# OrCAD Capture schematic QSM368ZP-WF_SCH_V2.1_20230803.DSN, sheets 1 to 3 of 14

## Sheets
1 PAGE01-POWER: size A2; rev: V2.1
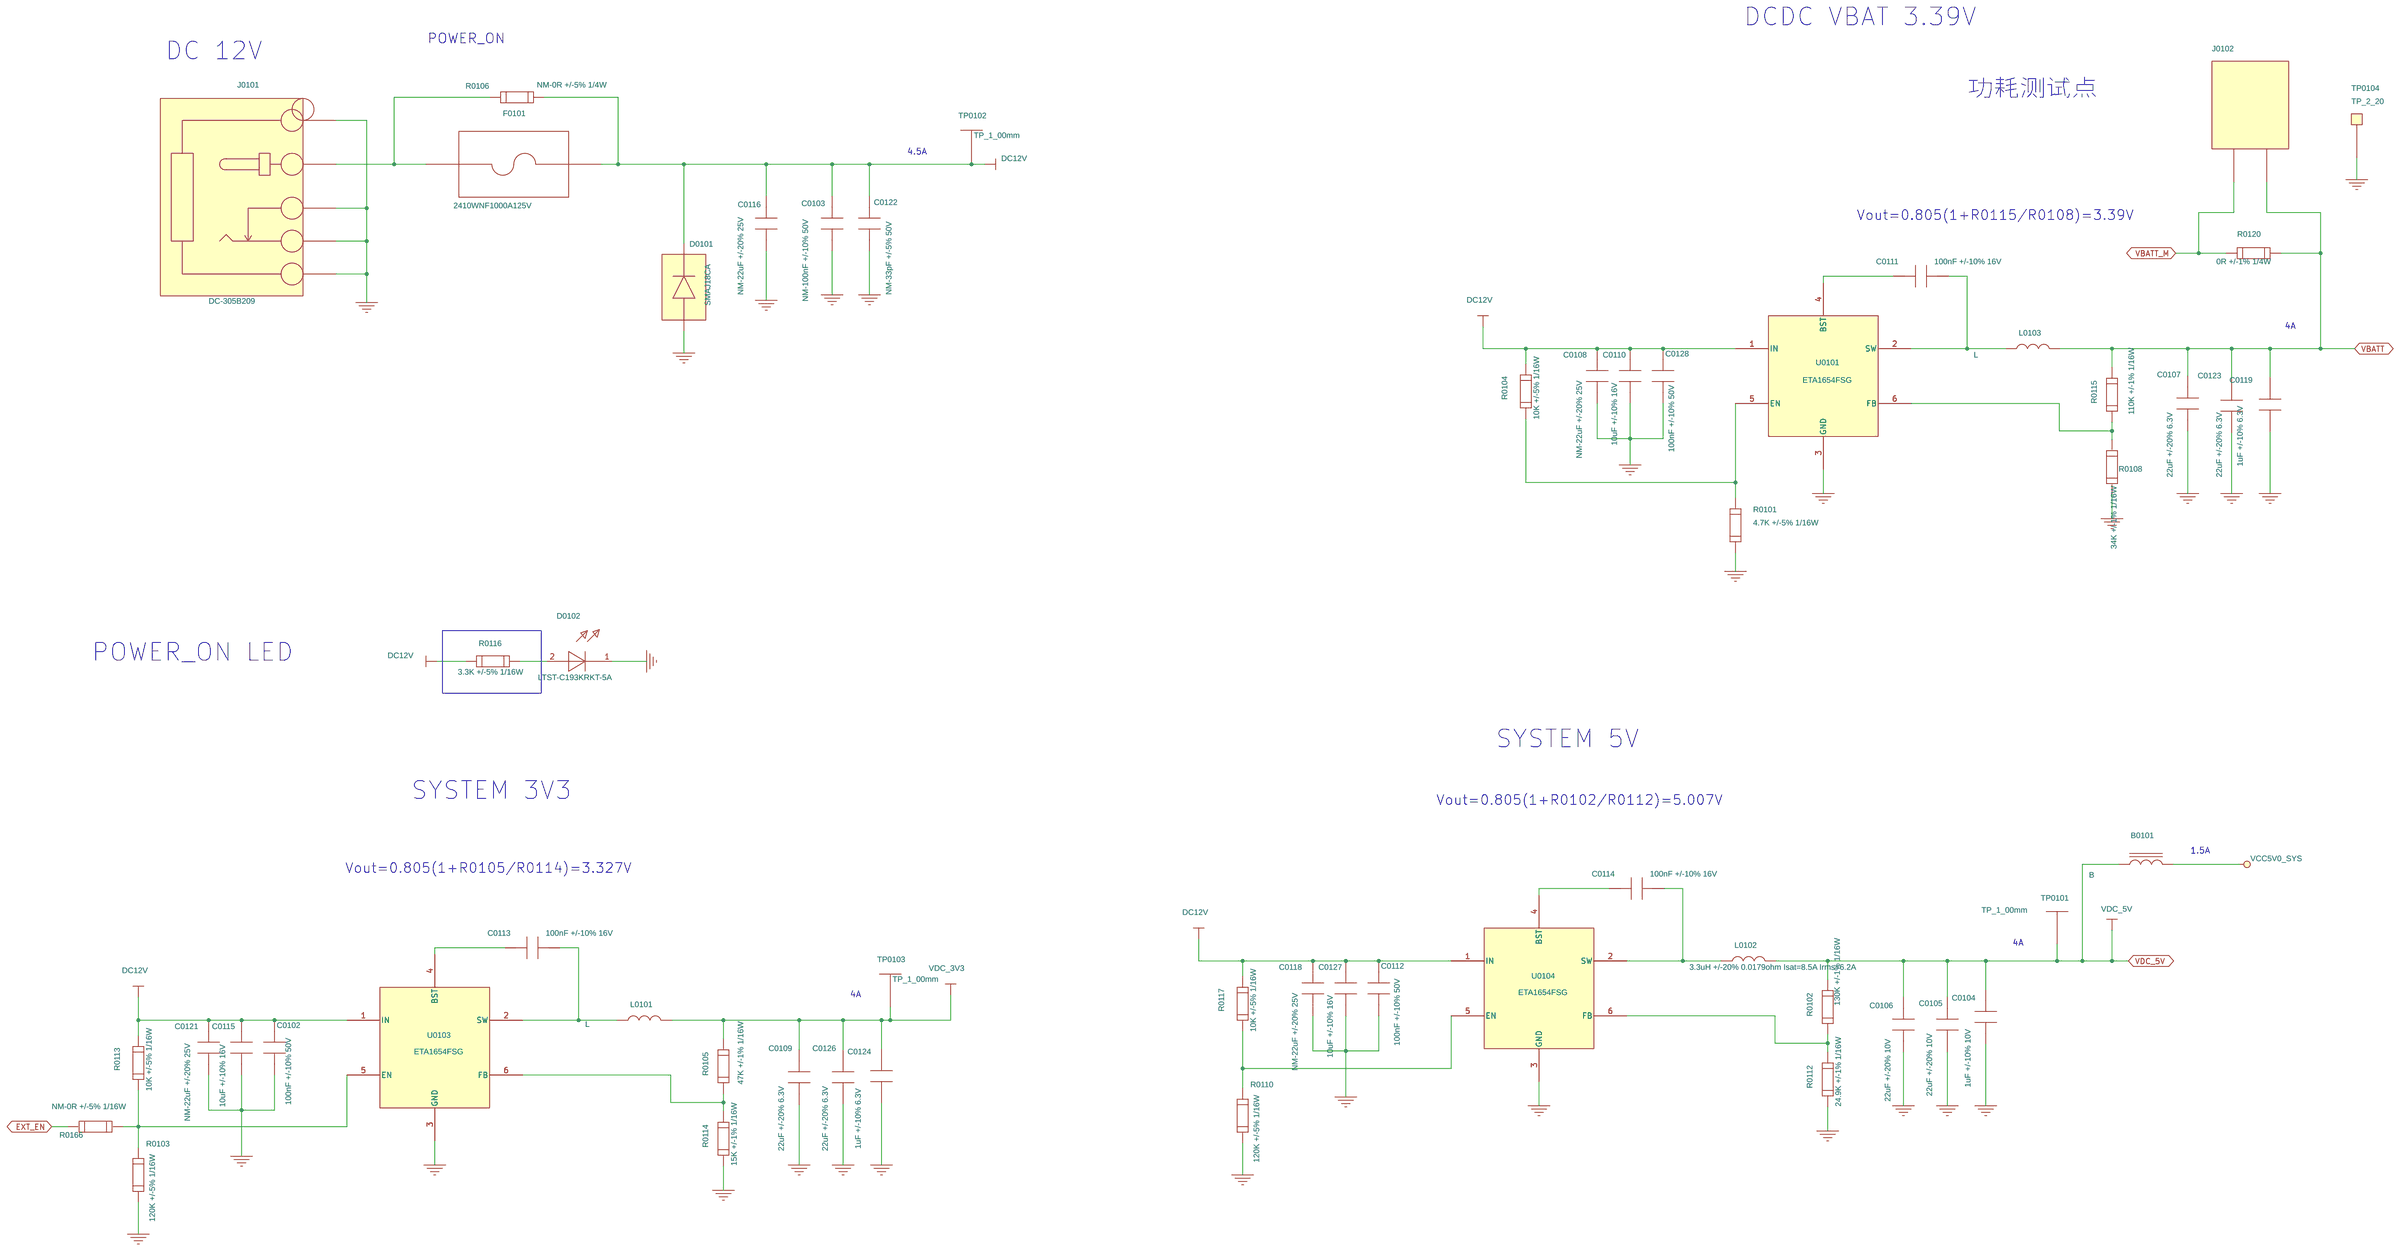
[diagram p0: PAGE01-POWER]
2 PAGE02-CAMERA: size A2
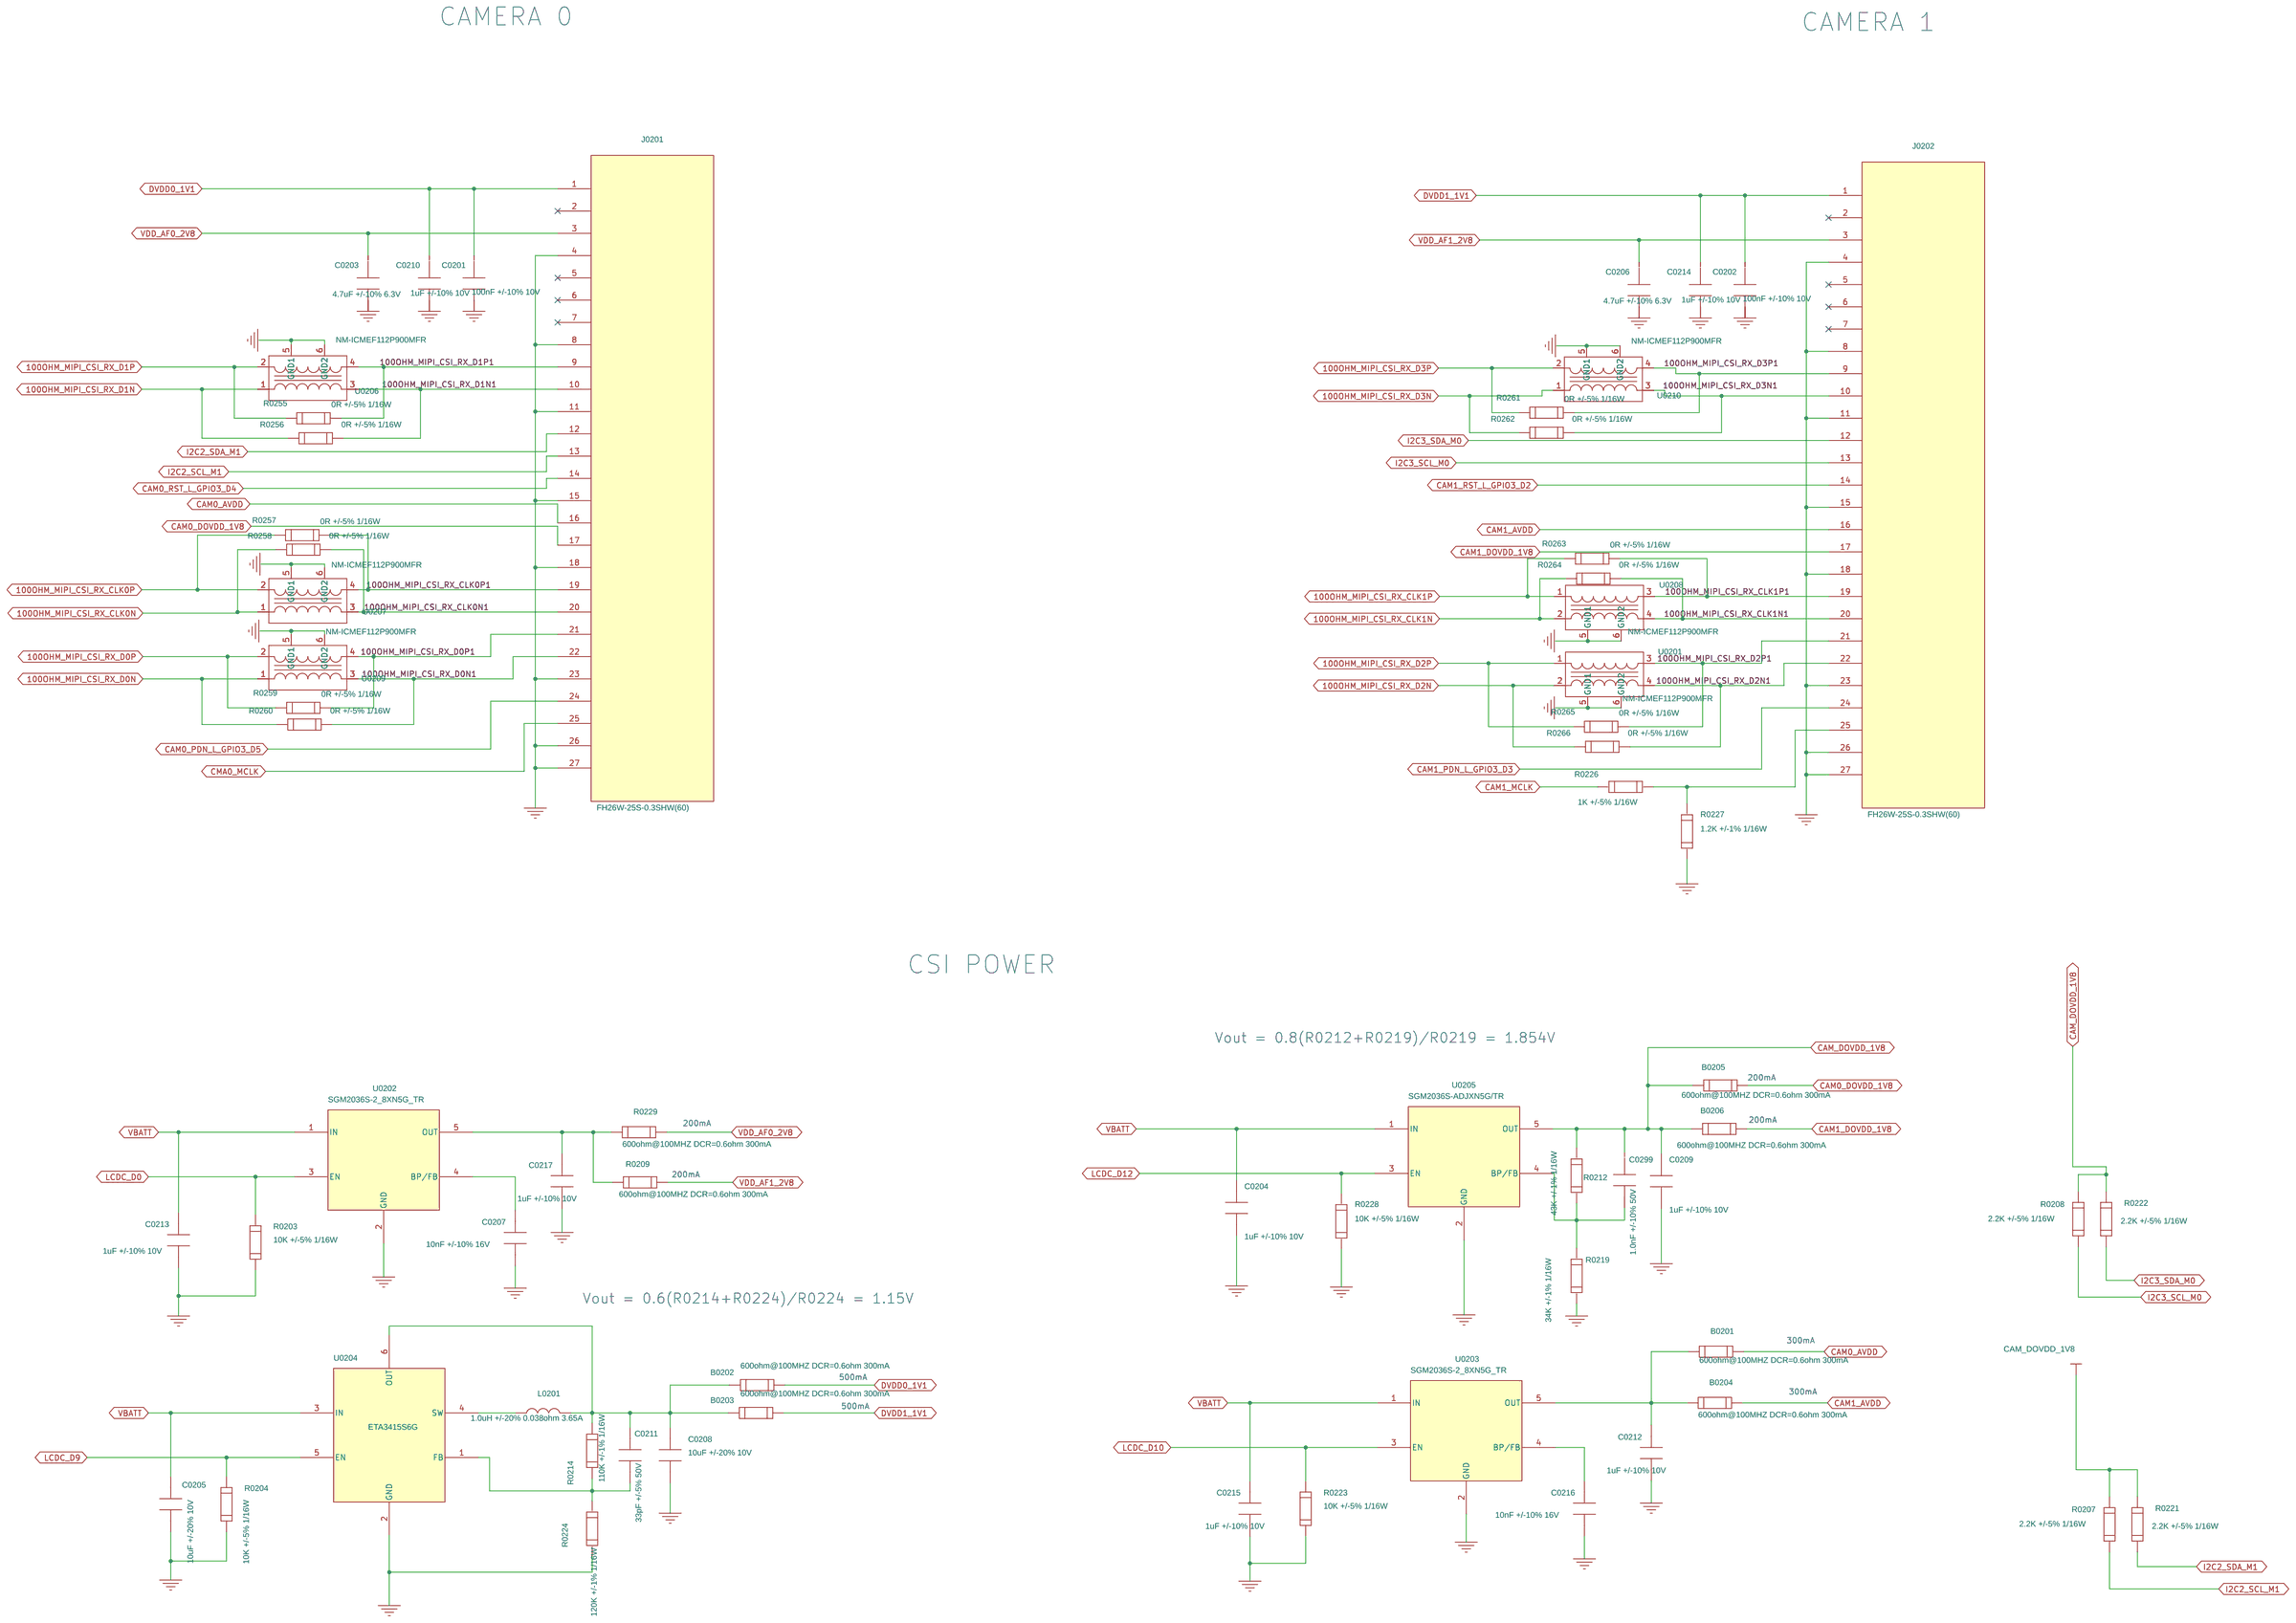
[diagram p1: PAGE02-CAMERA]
3 PAGE03-USB-OTG: size A2
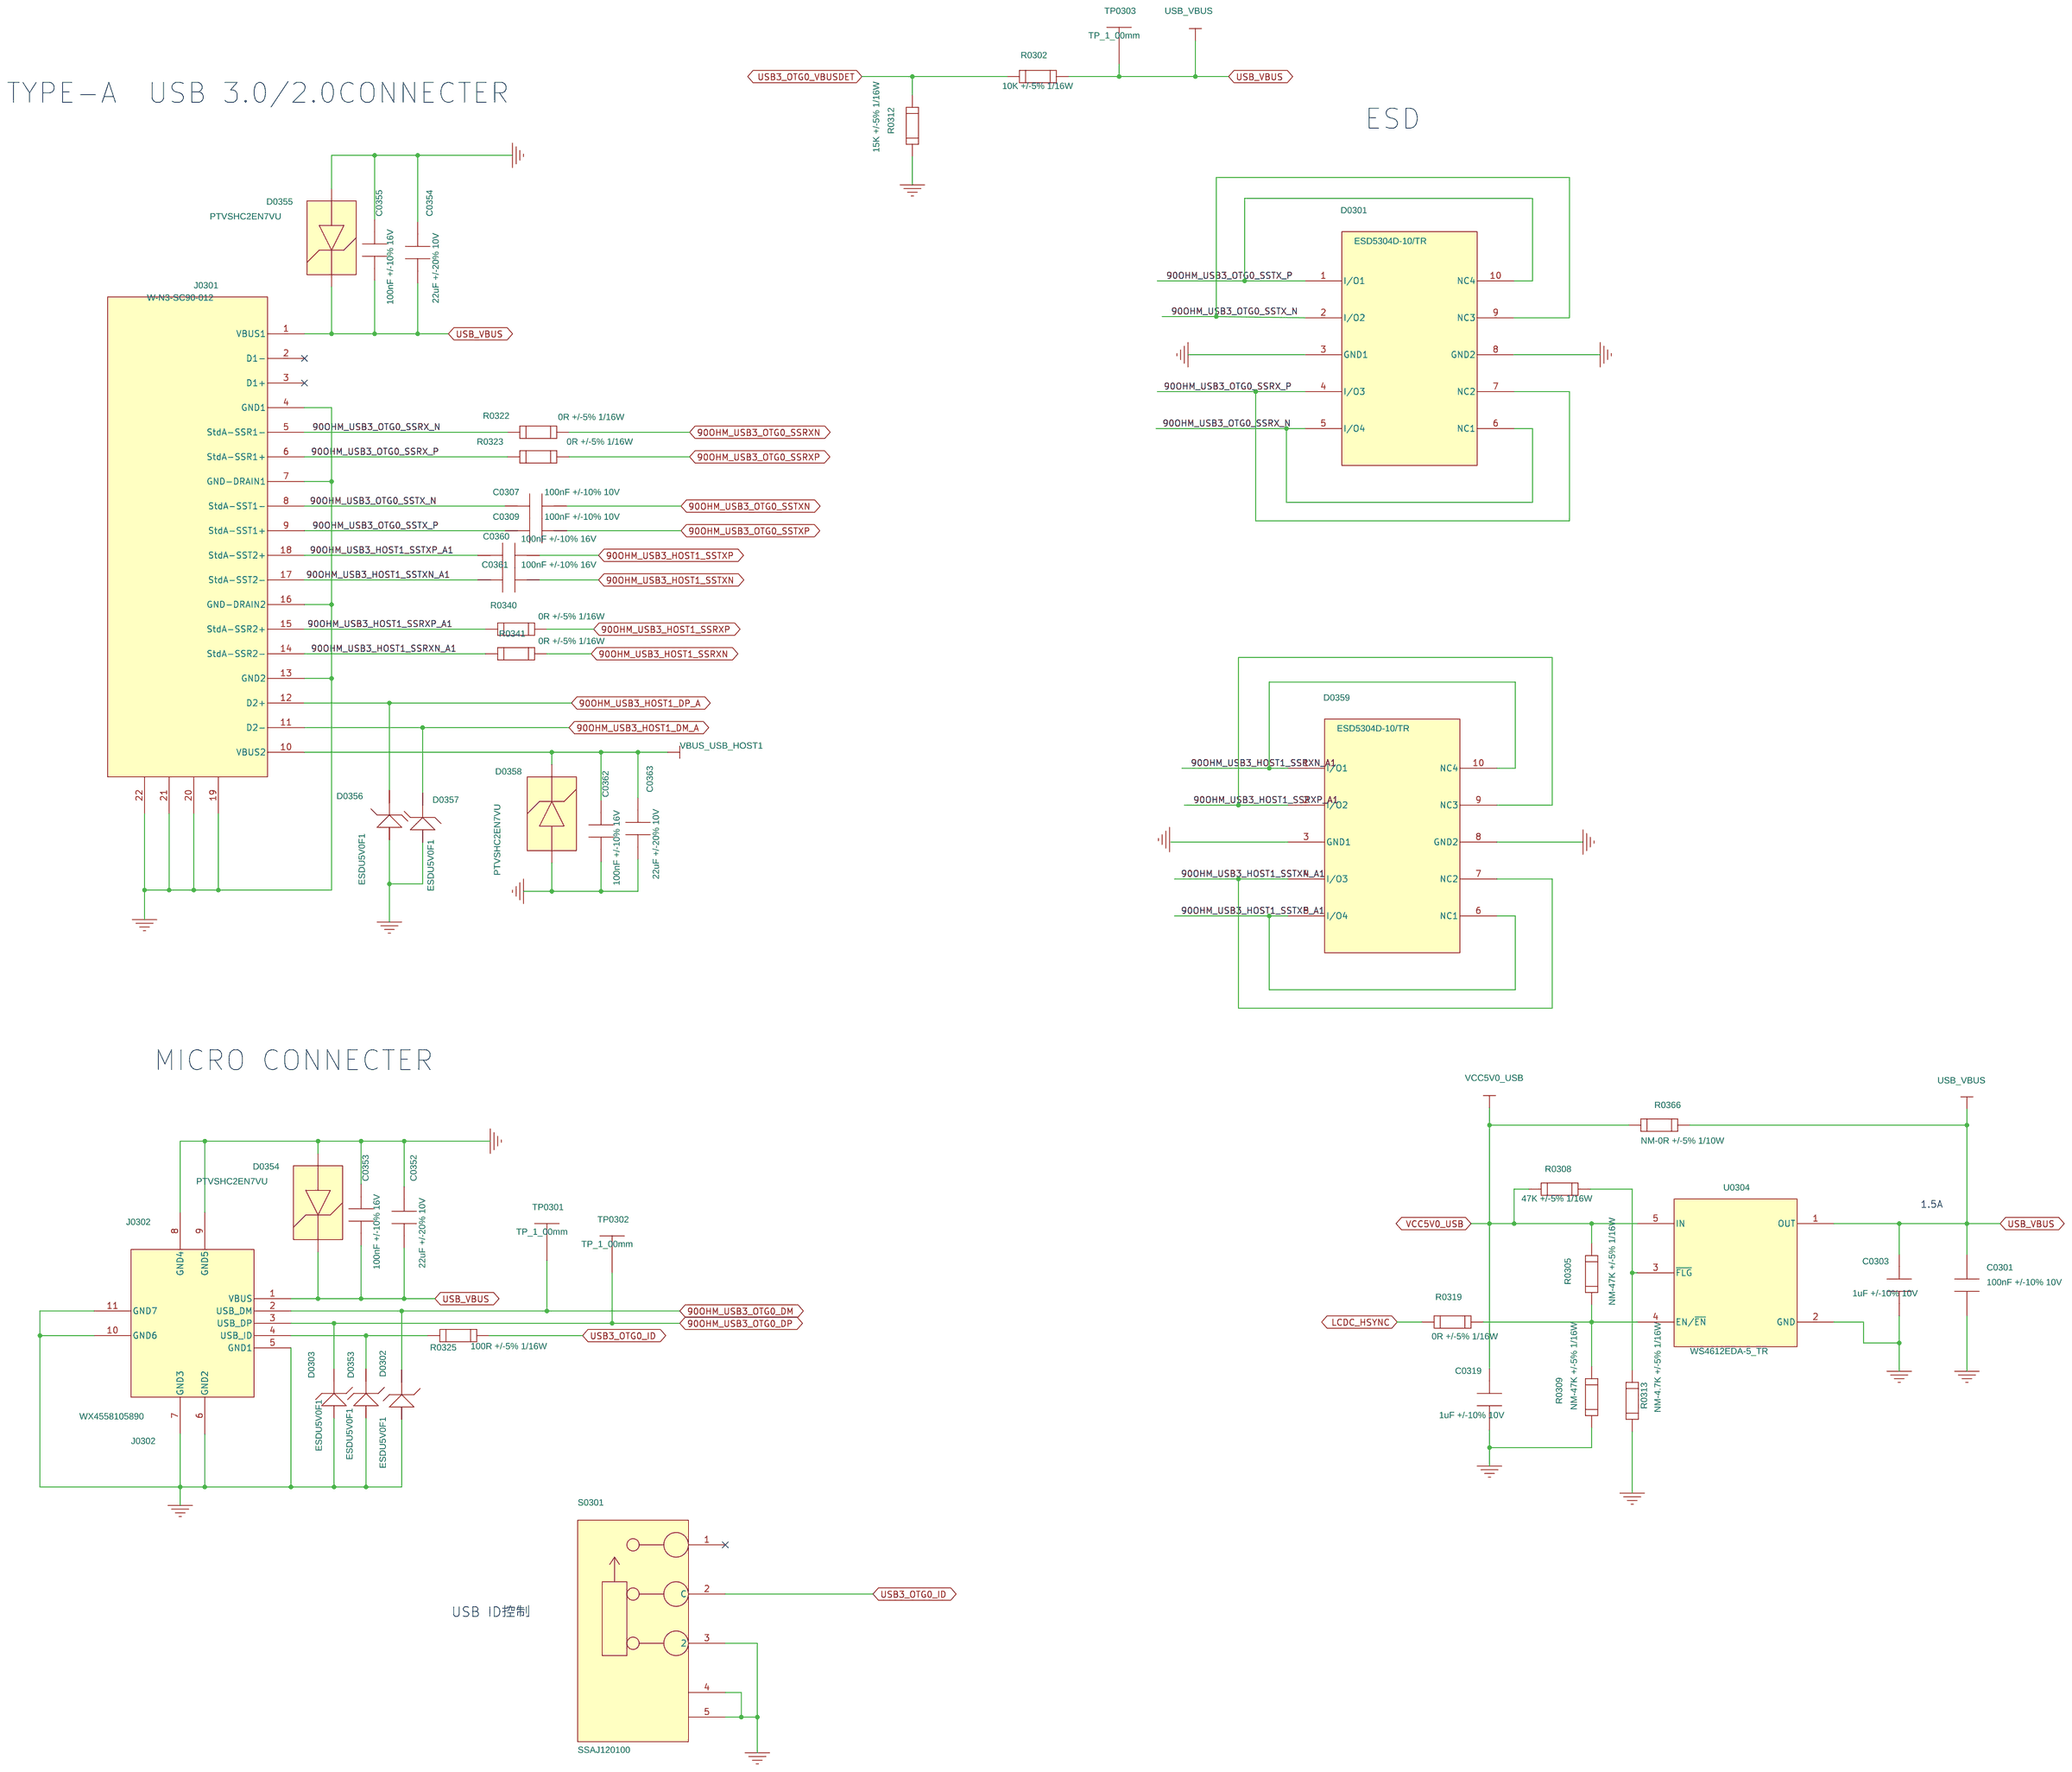
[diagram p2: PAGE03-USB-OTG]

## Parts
sheet PAGE01-POWER
B0101  B  [B-0402]
C0102  100nF +/-10% 50V  [C-0603]
C0103  NM-100nF +/-10% 50V  [C-0603]
C0104  1uF +/-10% 10V  [C-0402]
C0105  22uF +/-20% 10V  [c-0603_22_47uf_h1_00]
C0106  22uF +/-20% 10V  [c-0603_22_47uf_h1_00]
C0107  22uF +/-20% 6.3V  [c-0603_22_47uf_h1_00]
C0108  NM-22uF +/-20% 25V  [C-0805_H1_45]
C0109  22uF +/-20% 6.3V  [c-0603_22_47uf_h1_00]
C0110  10uF +/-10% 16V  [C-0805_H1_45]
C0111  100nF +/-10% 16V  [C-0402]
C0112  100nF +/-10% 50V  [C-0603]
C0113  100nF +/-10% 16V  [C-0402]
C0114  100nF +/-10% 16V  [C-0402]
C0115  10uF +/-10% 16V  [C-0805_H1_45]
C0116  NM-22uF +/-20% 25V  [C-0805_H1_45]
C0118  NM-22uF +/-20% 25V  [C-0805_H1_45]
C0119  1uF +/-10% 6.3V  [C-0402]
C0121  NM-22uF +/-20% 25V  [C-0805_H1_45]
C0122  NM-33pF +/-5% 50V  [C-0402]
C0123  22uF +/-20% 6.3V  [c-0603_22_47uf_h1_00]
C0124  1uF +/-10% 6.3V  [C-0402]
C0126  22uF +/-20% 6.3V  [c-0603_22_47uf_h1_00]
C0127  10uF +/-10% 16V  [C-0805_H1_45]
C0128  100nF +/-10% 50V  [C-0603]
D0101  SMAJ18CA  [SMAJ18CA]
D0102  LTST-C193KRKT-5A  [LTST-C193KRKT-5A]
F0101  2410WNF1000A125V  [2410WNF1000A125V]
J0101  DC-305B209  [DC-305B209]
J0102  NM-C2542VD10210G0101PK  [C2542VD10210G0101PK]
L0101  L  [L-SPM6530T-3R3M]
L0102  3.3uH +/-20% 0.0179ohm Isat=8.5A Irms=6.2A  [L-SPM6530T-3R3M]
L0103  L  [L-SPM6530T-3R3M]
R0101  4.7K +/-5% 1/16W  [R-0402]
R0102  130K +/-1% 1/16W  [R-0402]
R0103  120K +/-5% 1/16W  [R-0402]
R0104  10K +/-5% 1/16W  [R-0402]
R0105  47K +/-1% 1/16W  [R-0402]
R0106  NM-0R +/-5% 1/4W  [R-1206]
R0108  34K +/-1% 1/16W  [R-0402]
R0110  120K +/-5% 1/16W  [R-0402]
R0112  24.9K +/-1% 1/16W  [R-0402]
R0113  10K +/-5% 1/16W  [R-0402]
R0114  15K +/-1% 1/16W  [R-0402]
R0115  110K +/-1% 1/16W  [R-0402]
R0116  3.3K +/-5% 1/16W  [R-0402]
R0117  10K +/-5% 1/16W  [R-0402]
R0120  0R +/-1% 1/4W  [R-1206]
R0166  NM-0R +/-5% 1/16W  [R-0402]
TP0101  TP_1_00mm  [TP_1_00]
TP0102  TP_1_00mm  [TP_1_00]
TP0103  TP_1_00mm  [TP_1_00]
TP0104  TP_2_20  [TP_2_20]
U0101  ETA1654FSG  [ETA1654FSG]
U0103  ETA1654FSG  [ETA1654FSG]
U0104  ETA1654FSG  [ETA1654FSG]
sheet PAGE02-CAMERA
B0201  600ohm@100MHZ DCR=0.6ohm 300mA  [R-0402]
B0202  600ohm@100MHZ DCR=0.6ohm 300mA  [R-0402]
B0203  600ohm@100MHZ DCR=0.6ohm 300mA  [R-0402]
B0204  600ohm@100MHZ DCR=0.6ohm 300mA  [R-0402]
B0205  600ohm@100MHZ DCR=0.6ohm 300mA  [R-0402]
B0206  600ohm@100MHZ DCR=0.6ohm 300mA  [R-0402]
C0201  100nF +/-10% 10V  [C-0402]
C0202  100nF +/-10% 10V  [C-0402]
C0203  4.7uF +/-10% 6.3V  [C-0603]
C0204  1uF +/-10% 10V  [C-0402]
C0205  10uF +/-20% 10V  [c-0402_4_7_10uf_H0_70]
C0206  4.7uF +/-10% 6.3V  [C-0603]
C0207  10nF +/-10% 16V  [C-0402]
C0208  10uF +/-20% 10V  [c-0402_4_7_10uf_H0_70]
C0209  1uF +/-10% 10V  [C-0402]
C0210  1uF +/-10% 10V  [C-0402]
C0211  33pF +/-5% 50V  [C-0402]
C0212  1uF +/-10% 10V  [C-0402]
C0213  1uF +/-10% 10V  [C-0402]
C0214  1uF +/-10% 10V  [C-0402]
C0215  1uF +/-10% 10V  [C-0402]
C0216  10nF +/-10% 16V  [C-0402]
C0217  1uF +/-10% 10V  [C-0402]
C0299  1.0nF +/-10% 50V  [C-0402]
J0201  FH26W-25S-0.3SHW(60)  [fh26w-25s-0_3shw_60]
J0202  FH26W-25S-0.3SHW(60)  [fh26w-25s-0_3shw_60]
L0201  1.0uH +/-20% 0.038ohm 3.65A  [L-2016]
R0203  10K +/-5% 1/16W  [R-0402]
R0204  10K +/-5% 1/16W  [R-0402]
R0207  2.2K +/-5% 1/16W  [R-0402]
R0208  2.2K +/-5% 1/16W  [R-0402]
R0209  600ohm@100MHZ DCR=0.6ohm 300mA  [R-0402]
R0212  43K +/-1% 1/16W  [R-0402]
R0214  110K +/-1% 1/16W  [R-0402]
R0219  34K +/-1% 1/16W  [R-0402]
R0221  2.2K +/-5% 1/16W  [R-0402]
R0222  2.2K +/-5% 1/16W  [R-0402]
R0223  10K +/-5% 1/16W  [R-0402]
R0224  120K +/-1% 1/16W  [R-0402]
R0226  1K +/-5% 1/16W  [R-0402]
R0227  1.2K +/-1% 1/16W  [R-0402]
R0228  10K +/-5% 1/16W  [R-0402]
R0229  600ohm@100MHZ DCR=0.6ohm 300mA  [R-0402]
R0255  0R +/-5% 1/16W  [R-0402]
R0256  0R +/-5% 1/16W  [R-0402]
R0257  0R +/-5% 1/16W  [R-0402]
R0258  0R +/-5% 1/16W  [R-0402]
R0259  0R +/-5% 1/16W  [R-0402]
R0260  0R +/-5% 1/16W  [R-0402]
R0261  0R +/-5% 1/16W  [R-0402]
R0262  0R +/-5% 1/16W  [R-0402]
R0263  0R +/-5% 1/16W  [R-0402]
R0264  0R +/-5% 1/16W  [R-0402]
R0265  0R +/-5% 1/16W  [R-0402]
R0266  0R +/-5% 1/16W  [R-0402]
U0201  NM-ICMEF112P900MFR  [ICMEF112P900MFR]
U0202  SGM2036S-2_8XN5G_TR  [SGM2036S-2_8XN5G_TR_PINS5_2D92X1D6]
U0203  SGM2036S-2_8XN5G_TR  [SGM2036S-2_8XN5G_TR_PINS5_2D92X1D6]
U0204  ETA3415S6G  [ETA3415S6G]
U0205  SGM2036S-ADJXN5G/TR  [SGM2036S-ADJXN5G_TR_PINS5_2D92X1D6]
U0206  NM-ICMEF112P900MFR  [ICMEF112P900MFR]
U0207  NM-ICMEF112P900MFR  [ICMEF112P900MFR]
U0208  NM-ICMEF112P900MFR  [ICMEF112P900MFR]
U0209  NM-ICMEF112P900MFR  [ICMEF112P900MFR]
U0210  NM-ICMEF112P900MFR  [ICMEF112P900MFR]
sheet PAGE03-USB-OTG
C0301  100nF +/-10% 10V  [C-0402]
C0303  1uF +/-10% 10V  [C-0402]
C0307  100nF +/-10% 10V  [C-0402]
C0309  100nF +/-10% 10V  [C-0402]
C0319  1uF +/-10% 10V  [C-0402]
C0352  22uF +/-20% 10V  [c-0603_22_47uf_h1_00]
C0353  100nF +/-10% 16V  [C-0402]
C0354  22uF +/-20% 10V  [c-0603_22_47uf_h1_00]
C0355  100nF +/-10% 16V  [C-0402]
C0360  100nF +/-10% 16V  [C-0402]
C0361  100nF +/-10% 16V  [C-0402]
C0362  100nF +/-10% 16V  [C-0402]
C0363  22uF +/-20% 10V  [c-0603_22_47uf_h1_00]
D0301  ESD5304D-10/TR  [ESD5304D-10_TR]
D0302  ESDU5V0F1  [ESDU5V0F1]
D0303  ESDU5V0F1  [ESDU5V0F1]
D0353  ESDU5V0F1  [ESDU5V0F1]
D0354  PTVSHC2EN7VU  [PTVSHC2EN7VU]
D0355  PTVSHC2EN7VU  [PTVSHC2EN7VU]
D0356  ESDU5V0F1  [ESDU5V0F1]
D0357  ESDU5V0F1  [ESDU5V0F1]
D0358  PTVSHC2EN7VU  [PTVSHC2EN7VU]
D0359  ESD5304D-10/TR  [ESD5304D-10_TR]
J0301  W-N3-SC90-012  [W-N3-SC90-012]
J0302  WX4558105890  [WX4558105890]
R0302  10K +/-5% 1/16W  [R-0402]
R0305  NM-47K +/-5% 1/16W  [R-0402]
R0308  47K +/-5% 1/16W  [R-0402]
R0309  NM-47K +/-5% 1/16W  [R-0402]
R0312  15K +/-5% 1/16W  [R-0402]
R0313  NM-4.7K +/-5% 1/16W  [R-0402]
R0319  0R +/-5% 1/16W  [R-0402]
R0322  0R +/-5% 1/16W  [R-0402]
R0323  0R +/-5% 1/16W  [R-0402]
R0325  100R +/-5% 1/16W  [R-0402]
R0340  0R +/-5% 1/16W  [R-0402]
R0341  0R +/-5% 1/16W  [R-0402]
R0366  NM-0R +/-5% 1/10W  [R-0603]
S0301  SSAJ120100  [SSAJ120100]
TP0301  TP_1_00mm  [TP_1_00]
TP0302  TP_1_00mm  [TP_1_00]
TP0303  TP_1_00mm  [TP_1_00]
U0304  WS4612EDA-5_TR  [WS4612EDA-5_TR]

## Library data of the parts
B0101 = B: Application_Level: 通用; DataRecord: 2023-01-04; Lib_Name: 电感&磁珠; MPN: UPB100505T-121Y-N; Manufacturer: CHILISIN; Part Description: BEAD 120ohm@100MHz DCR=0.055ohm 2.0A CH0402 H0.6mm RO; Part Number: QME014100031; Rev.Date: 2023-01-04
C0102 C0112 C0128 = C: Application_Level: Non-common(非通用); DataRecord: 2017-08-09; Geometry Height: 0.8mm; Lib_Name: 电容; MPN: CC0603KRX7R9BB104; Manufacturer: YAGEO; Part Description: CAP X7R 100nF +/-10% 50V CH0603 H0.9mm RO; Part Number: QT0012000587; Rev.Date: 2022-08-17
C0103 = C: Application_Level: Non-common(非通用); BOMRemark: NM; DataRecord: 2017-08-09; Geometry Height: 0.8mm; Lib_Name: 电容; MPN: CC0603KRX7R9BB104; Manufacturer: YAGEO; Part Description: CAP X7R 100nF +/-10% 50V CH0603 H0.9mm RO; Part Number: QT0012000587; Rev.Date: 2021-12-15
C0104 = C: Application_Level: 通用; DataRecord: 2017-08-09; Geometry Height: 0.5mm; Lib_Name: 电容; MPN: CC0402KRX5R6BB105; Manufacturer: YAGEO; Part Description: CAP X5R 1uF +/-10% 10V CH0402 H0.55mm RO; Part Number: QT0012000349; Rev.Date: 2022-08-17
C0105 C0106 C0352 C0354 C0363 = c-0603_22_47uf_H1_00: Application_Level: 通用; DataRecord: 2017-08-09; Geometry Height: 1.0mm; Lib_Name: 电容; MPN: CC0603MRX5R6BB226; Manufacturer: YAGEO; Part Description: CAP X5R 22uF +/-20% 10V CH0603 1.6x0.8mm H1mm RO; Part Number: QT0012102005; Rev.Date: 2022-09-21
C0107 C0109 C0123 C0126 = c-0603_22_47uf_H1_00: Application_Level: 通用; DataRecord: 2017-08-09; Geometry Height: 1MM; Lib_Name: 电容; MPN: CC0603MRX5R5BB226; Manufacturer: YAGEO; Part Description: CAP X5R 22uF +/-20% 6.3V CH0603 1.6x0.8mm H1mm RO; Part Number: QT0012000626; Rev.Date: 2022-09-21
C0108 C0116 C0118 C0121 = C-0805_H1_45: Application_Level: Limited(限制); BOMRemark: NM; DataRecord: 2020-01-09; Geometry Height: 1.45mm; Lib_Name: 电容; MPN: GRM21BR61E226ME44L; Manufacturer: MURATA; Part Description: CAP X5R 22uF +/-20% 25V CH0805 H1.45mm RO; Part Number: QT0012002582; Rev.Date: 2021-10-25
C0110 C0115 C0127 = C-0805_H1_45: Application_Level: Common(通用); DataRecord: 2017-08-09; Geometry Height: 1.45mm; Lib_Name: 电容; MPN: CC0805KKX5R7BB106; Manufacturer: YAGEO; Part Description: CAP X5R 10uF +/-10% 16V CH0805 2.0x1.25mm H1.45mm RO; Part Number: QT0012001358; Rev.Date: 2022-09-21
C0111 C0113 C0114 = C: Application_Level: Non-common(非通用); DataRecord: 2017-08-09; Geometry Height: 0.5mm; Lib_Name: 电容; MPN: CC0402KRX7R7BB104; Manufacturer: YAGEO; Part Description: CAP X7R 100nF +/-10% 16V CH0402 H0.55mm RO; Part Number: QT0012100748; Rev.Date: 2022-08-17
C0119 C0124 = C: Application_Level: 通用; DataRecord: 2017-08-09; Geometry Height: 0.5mm; Lib_Name: 电容; MPN: CC0402KRX5R5BB105; Manufacturer: YAGEO; Part Description: CAP X5R 1uF +/-10% 6.3V CH0402 H0.55mm RO; Part Number: QT0012100534; Rev.Date: 2022-08-17
C0122 = C: Application_Level: Non-common(非通用); BOMRemark: NM; DataRecord: 2017-08-09; Geometry Height: 0.5mm; Lib_Name: 电容; MPN: CC0402JRNPO9BN330; Manufacturer: YAGEO; Part Description: CAP C0G 33pF +/-5% 50V CH0402 H0.55mm RO; Part Number: QT0012100261; Rev.Date: 2021-12-15
D0101 = SMAJ18CA: Application_Level: Limited(限制); DataRecord: 2017-08-09; Geometry Height: 2.62mm; Lib_Name: ESD&EMI&TVS; Manufacturer: DIODES; Part Description: TVS SI Vr=18V  300pF DO-214AC RO; Part Number: QT0013501021; Rev.Date: 2022-10-18
D0102 = LTST-C193KRKT-5A: Application_Level: 通用; DataRecord: 2017-08-09; Geometry Height: 0.35mm; Lib_Name: LED; Manufacturer: LITEON; Part Description: DIO LED RED VF=2.0V CH0603 RO; Part Number: QT0015300052; Rev.Date: 2022-08-17
F0101 = 2410WNF1000A125V: Application_Level: Common(通用); DataRecord: 2020-06-03; Geometry Height: 3.0mm; Lib_Name: 熔断保险丝; Manufacturer: WAYON; Part Description: FUSE 10A 125V 6.5x2.8mm H3.0mm RO; Part Number: QT0026401005; Rev.Date: 2023-06-05
J0101 = DC-305B209: Application_Level: Common(通用); BOMRemark: NSMT; DataRecord: 2022-05-30; Geometry Height: 10.19mm; Lib_Name: 结构连接器; Manufacturer: DAWEI; Part Description: CON DC POWER JACK Pin1=Pin2=Pin3=1.4mm Pin4=1.8mm RO; Part Number: QT0016201726; Rev.Date: 2022-08-17
J0102 = C2542VD10210G0101PK: Application_Level: Common(通用); BOMRemark: NM; DataRecord: 2021-03-05; Geometry Height: 11.75mm; Lib_Name: 结构连接器; Manufacturer: KONNRA; Part Description: CON DIP PIN HEADER 1x2PIN 2.54pitch H11.75mm 180° HH PA6T RO; Part Number: QT0016201439; Rev.Date: 2021-10-25
L0101 L0103 = L: Application_Level: Common(通用); DataRecord: 2023-04-12; Lib_Name: 电感&磁珠; MPN: AIP0630MB-2R2M; Manufacturer: INPAQ; Part Description: IND LOW 2.2uH +/-20% 0.015ohm 8.0A 7.0x6.6mm H3.0mm RO; Part Number: QT0014104151; Rev.Date: 2023-04-21
L0102 = L: Application_Level: Common(通用); DataRecord: 2023-04-11; Geometry Height: 3; Lib_Name: 电感&磁珠; MPN: AIP0630MB-3R3M; Manufacturer: INPAQ; Part Description: IND LOW 3.3uH +/-20% 0.0179ohm 6.2A 7x6.6mm H3mm RO; Part Number: QT0014104150; Rev.Date: 2023-04-11; SCH Part: L-AIP0630MB
R0101 = R-0402: Application_Level: Common(通用); DataRecord: 2017-08-09; Geometry Height: 0.4MM; Lib_Name: 电阻; MPN: RC0402JR-074K7L; Manufacturer: YAGEO; Part Description: RES MF 4.7K +/-5% 1/16W CH0402 H0.4mm RO; Part Number: QT0011000456; Rev.Date: 2022-08-17
R0102 = R-0402: Application_Level: Common(通用); DataRecord: 2017-08-09; Geometry Height: 0.4MM; Lib_Name: 电阻; MPN: RC0402FR-07130KL; Manufacturer: YAGEO; Part Description: RES MF 130K +/-1% 1/16W CH0402 H0.4mm RO; Part Number: QT0011003182; Rev.Date: 2022-08-17
R0103 R0110 = R-0402: Application_Level: Common(通用); DataRecord: 2017-08-09; Geometry Height: 0.4MM; Lib_Name: 电阻; MPN: RC0402JR-07120KL; Manufacturer: YAGEO; Part Description: RES MF 120K +/-5% 1/16W CH0402 H0.4mm RO; Part Number: QT0011000521; Rev.Date: 2022-08-17
R0104 R0113 R0117 = R-0402: Application_Level: Common(通用); DataRecord: 2017-08-09; Geometry Height: 0.4MM; Lib_Name: 电阻; MPN: RC0402JR-0710KL; Manufacturer: YAGEO; Part Description: RES MF 10K +/-5% 1/16W CH0402 H0.4mm RO; Part Number: QT0011000453; Rev.Date: 2022-08-17
R0105 = R-0402: Application_Level: Common(通用); DataRecord: 2017-08-09; Geometry Height: 0.4MM; Lib_Name: 电阻; MPN: RC0402FR-0747KL; Manufacturer: YAGEO; Part Description: RES MF 47K +/-1% 1/16W CH0402 H0.4mm RO; Part Number: QT0011000177; Rev.Date: 2022-08-17
R0106 = R-1206: Application_Level: Common(通用); BOMRemark: NM; DataRecord: 2019-08-28; Geometry Height: 0.65mm; Lib_Name: 电阻; MPN: RC1206JR-070RL; Manufacturer: YAGEO; Part Description: RES MF 0R +/-5% 1/4W CH1206 H0.65mm RO; Part Number: QT0011003640; Rev.Date: 2021-12-15
R0108 R0219 = R-0402_v3: DataRecord: 2020-02-29; MPN: RC-02W3402FT; Manufacturer: FENGHUA; Part Description: RES MF 34K +/-1% 1/16W CH0402 RO; Part Number: QT0011003963; Rev.Date: 2022-08-17
R0112 = R-0402: Application_Level: Common(通用); DataRecord: 2017-08-09; Geometry Height: 0.4MM; Lib_Name: 电阻; MPN: RC0402FR-0724K9L; Manufacturer: YAGEO; Part Description: RES MF 24.9K +/-1% 1/16W CH0402 H0.4mm RO; Part Number: QT0011003145; Rev.Date: 2022-08-17
R0114 = R-0402: Application_Level: Common(通用); DataRecord: 2017-08-09; Geometry Height: 0.4MM; Lib_Name: 电阻; MPN: RC0402FR-0715KL; Manufacturer: YAGEO; Part Description: RES MF 15K +/-1% 1/16W CH0402 H0.4mm RO; Part Number: QT0011000103; Rev.Date: 2022-08-17
R0115 R0214 = R-0402: Application_Level: Common(通用); DataRecord: 2017-08-09; Geometry Height: 0.4mm; Lib_Name: 电阻; MPN: RC0402FR-07110KL; Manufacturer: YAGEO; Part Description: RES MF 110K +/-1% 1/16W CH0402 H0.4mm RO; Part Number: QT0011000463; Rev.Date: 2022-08-17
R0116 = R-0402_0R: DataRecord: 2017-08-09; Geometry Height: 0.4mm; MPN: RC0402JR-073K3L; Part Description: RES MF 3.3K +/-5% 1/16W CH0402 H0.4mm RO; Part Number: QT0011000024; Rev.Date: 2022-08-17
R0120 = R-1206: Application_Level: 通用; DataRecord: 2017-08-09; Geometry Height: 0.65mm; Lib_Name: 电阻; MPN: RC1206FR-070RL; Manufacturer: YAGEO; Part Description: RES MF 0R +/-1% 1/4W CH1206 H0.65mm RO; Part Number: QT0011003051; Rev.Date: 2022-08-17
R0166 = R-0402_v3: BOMRemark: NM; Manufacturer: YAGEO; Part Description: RES MF 0R +/-5% 1/16W CH0402 RO; Part Number: QT0011000094
TP0101 TP0102 TP0103 TP0301 TP0302 TP0303 = TP_1_00: option: @
TP0104 = TP_2_20: option: @
U0101 U0103 U0104 = ETA1654FSG: Application_Level: 通用; DataRecord: 2021-11-26; Geometry Height: 0.6mm; Lib_Name: 电源管理芯片; Manufacturer: ETA; Part Description: PMIC DC-DC BUCK 4.5-18V ADJ 600KHz 4A 230uA SOT-563-6 1.6x1.6mm H0.6mm RO; Part Number: QT0013101598; Rev.Date: 2022-08-17
B0201 B0202 B0203 B0204 B0205 B0206 R0209 R0229 = R-0402_0R: DataRecord: 2017-08-09; Geometry Height: 0.55mm; MPN: BK1005HW601-T; Manufacturer: TAIYO; Part Description: BEAD 600ohm@100MHZ DCR=0.6ohm 300mA CH0402 H0.5mm RO; Part Number: QT0014101548; Rev.Date: 2022-08-17; SCH Part: B
C0201 C0202 = C-0402_v2: DataRecord: 2017-08-09; Geometry Height: 0.5mm; MPN: CC0402KRX7R6BB104; Manufacturer: YAGEO; Part Description: CAP X7R 100nF +/-10% 10V CH0402 H0.55mm RO; Part Number: QT0012000328; Rev.Date: 2022-08-17; SCH Part: C
C0203 C0206 = C-0603: DataRecord: 2017-08-09; Geometry Height: 0.8mm; Geometry.Height: 0.5mm; MPN: CC0603KRX5R5BB475; Manufacturer: YAGEO; Part Description: CAP X5R 4.7uF +/-10% 6.3V CH0603 H0.9mm RO; Part Number: QT0012100596; Rev.Date: 2022-08-17; SCH Part: C
C0204 C0209 C0212 C0213 C0215 C0217 = C-0402_X5R_10UF: DataRecord: 2017-08-09; Geometry Height: 0.5mm; MPN: CC0402KRX5R6BB105; Part Description: CAP X5R 1uF +/-10% 10V CH0402 H0.55mm RO; Part Number: QT0012000349; Rev.Date: 2022-08-17; SCH Part: C
C0205 C0208 = c-0402_4_7_10uf_H0_70: Application_Level: 通用; DataRecord: 2018-07-18; Geometry Height: 0.7MM; Lib_Name: 电容; MPN: GRM155R61A106ME11D; Manufacturer: MURATA; Part Description: CAP X5R 10uF +/-20% 10V CH0402 H0.7mm RO; Part Number: QT0012002415; Rev.Date: 2022-08-17
C0207 C0216 = C-0402_X5R_10UF: DataRecord: 2017-08-09; Geometry Height: 0.5mm; MPN: CC0402KRX7R7BB103; Part Description: CAP X7R 10nF +/-10% 16V CH0402 H0.55mm RO; Part Number: QT0012100289; Rev.Date: 2022-08-17; SCH Part: C
C0210 C0214 = C-0402_v2: DataRecord: 2017-08-09; Geometry Height: 0.5mm; MPN: CC0402KRX5R6BB105; Manufacturer: YAGEO; Part Description: CAP X5R 1uF +/-10% 10V CH0402 H0.55mm RO; Part Number: QT0012000349; Rev.Date: 2022-08-17; SCH Part: C
C0211 = C: Application_Level: Non-common(非通用); DataRecord: 2017-08-09; Geometry Height: 0.5mm; Lib_Name: 电容; MPN: CC0402JRNPO9BN330; Manufacturer: YAGEO; Part Description: CAP C0G 33pF +/-5% 50V CH0402 H0.55mm RO; Part Number: QT0012100261; Rev.Date: 2022-08-17
C0299 = C-0402_v2: DataRecord: 2017-08-09; Geometry Height: 0.5mm; MPN: CC0402KRX7R9BB102; Manufacturer: YAGEO; Part Description: CAP X7R 1.0nF +/-10% 50V CH0402 H0.55mm RO; Part Number: QT0012100276; Rev.Date: 2022-08-17; SCH Part: C
J0201 J0202 = FH26W-25S-0_3SHW_60: DataRecord: 2017-08-09; Geometry Height: 1.0mm; Manufacturer: HRS; Part Description: CON ZIF 25PIN 0.6pitch H1.0mm RO; Part Number: QT0016601001; Rev.Date: 2022-08-17
L0201 = L: Application_Level: 限制（Others）; DataRecord: 2018-01-18; Geometry Height: 1.0mm; Lib_Name: 电感&磁珠; MPN: WPN201610UF1R0MT; Manufacturer: SUNLORD; Part Description: IND LOW 1.0uH +/-20% 0.038ohm 3.65A 2.0x1.6mm H1.0mm RO; Part Number: QT0014103321; Rev.Date: 2022-08-17; SCH Part: L-WPN201610U
R0203 R0204 R0223 = R-0402_0R: DataRecord: 2017-08-09; Geometry Height: 0.4MM; MPN: RC0402JR-0710KL; Part Description: RES MF 10K +/-5% 1/16W CH0402 H0.4mm RO; Part Number: QT0011000453; Rev.Date: 2022-08-17
R0207 R0208 R0221 R0222 = R-0402: Application_Level: Common(通用); DataRecord: 2017-08-09; Geometry Height: 0.4MM; Lib_Name: 电阻; MPN: RC0402JR-072K2L; Manufacturer: YAGEO; Part Description: RES MF 2.2K +/-5% 1/16W CH0402 H0.4mm RO; Part Number: QT0011000522; Rev.Date: 2022-08-17
R0212 = R-0402_v3: Application_Level: 通用; DataRecord: 2017-08-09; Geometry Height: 0.4MM; Lib_Name: 电阻; MPN: RC0402FR-0743KL; Manufacturer: YAGEO; Part Description: RES MF 43K +/-1% 1/16W CH0402 H0.4mm RO; Part Number: QT0011000824; Rev.Date: 2022-08-17
R0224 = R-0402_v3: Application_Level: 通用; DataRecord: 2017-08-09; Geometry Height: 0.4MM; Lib_Name: 电阻; MPN: RC0402FR-07120KL; Manufacturer: YAGEO; Part Description: RES MF 120K +/-1% 1/16W CH0402 H0.4mm RO; Part Number: QT0011000101; Rev.Date: 2022-08-17
R0226 = R-0402_v3: DataRecord: 2017-08-09; Geometry Height: 0.4MM; MPN: RC0402JR-071KL; Manufacturer: YAGEO; Part Description: RES MF 1K +/-5% 1/16W CH0402 H0.4mm RO; Part Number: QT0011000489; Rev.Date: 2022-08-17
R0227 = R-0402_v3: DataRecord: 2019-10-30; Geometry Height: 0.4MM; MPN: RC0402FR-071K2L; Manufacturer: YAGEO; Part Description: RES MF 1.2K +/-1% 1/16W CH0402 H0.4mm RO; Part Number: QT0011003710; Rev.Date: 2022-08-17
R0228 = R-0402_v3: DataRecord: 2017-08-09; Geometry Height: 0.4MM; MPN: RC0402JR-0710KL; Manufacturer: YAGEO; Part Description: RES MF 10K +/-5% 1/16W CH0402 H0.4mm RO; Part Number: QT0011000453; Rev.Date: 2022-08-17
R0255 R0256 R0257 R0258 R0259 R0260 R0261 R0262 R0263 R0264 R0265 R0266 R0319 R0322 R0323 R0340 R0341 = R-0402: Application_Level: Common(通用); DataRecord: 2017-08-09; Geometry Height: 0.4MM; Lib_Name: 电阻; MPN: RC0402JR-070RL; Manufacturer: YAGEO; Part Description: RES MF 0R +/-5% 1/16W CH0402 H0.4mm RO; Part Number: QT0011000094; Rev.Date: 2022-08-17
U0201 U0206 U0207 U0208 U0209 U0210 = ICMEF112P900MFR: BOMRemark: NM; Geometry.Height: 0.65mm; Manufacturer: ICT; Part Description: ESD+EMI 2CH Wrwm=10V 0.8-1.7pF 0.1-3.0R 6Pin 1.0x1.27mm H0.65mm RO; Part Number: QT0013501003
U0202 U0203 = SGM2036S-2_8XN5G_TR: Application_Level: Common(通用); DataRecord: 2022-07-20; Geometry Height: 1.25mm; Lib_Name: 电源管理芯片; MPN: SGM2036S-2.8XN5G/TR; Manufacturer: SGMICRO; Part Description: PMIC LDO 1.6-5.5V 2.8V 300mA 25uA SOT23-5 2.8x2.92mm H1.25mm RO; Part Number: QT0013101651; Rev.Date: 2022-07-27
U0204 = ETA3415S6G: Application_Level: 通用; DataRecord: 2021-09-28; Geometry Height: 0.60mm; Lib_Name: 电源管理芯片; Manufacturer: ETA; Part Description: PMIC DC-DC BUCK 2.6-7V ADJ 3MHz 1A 40uA SOT563 1.7x1.7mm H0.6mm RO; Part Number: QT0013101576; Rev.Date: 2022-08-17
U0205 = SGM2036S-ADJXN5G_TR: Application_Level: Common(通用); DataRecord: 2022-09-05; Geometry Height: 1.25mm; Lib_Name: 电源管理芯片; Manufacturer: SGMICRO; Part Description: PMIC LDO 1.6-5.5V ADJ 300mA SOT23-5 PINS5 2.92x1.6mm H1.25mm RO; Part Number: QT0013101672; Rev.Date: 2022-09-14
C0301 = C: Application_Level: Common(通用); DataRecord: 2017-08-09; Geometry Height: 0.5mm; Lib_Name: 电容; MPN: CC0402KRX7R6BB104; Manufacturer: YAGEO; Part Description: CAP X7R 100nF +/-10% 10V CH0402 H0.55mm RO; Part Number: QT0012000328; Rev.Date: 2022-08-17
C0303 C0319 = C: Application_Level: Common(通用); DataRecord: 2017-08-09; Geometry Height: 0.5mm; Lib_Name: 电容; MPN: CC0402KRX5R6BB105; Manufacturer: YAGEO; Part Description: CAP X5R 1uF +/-10% 10V CH0402 H0.55mm RO; Part Number: QT0012000349; Rev.Date: 2022-08-17
C0307 C0309 = C: Application_Level: 通用; DataRecord: 2017-08-09; Geometry Height: 0.5mm; Lib_Name: 电容; MPN: CC0402KRX7R6BB104; Manufacturer: YAGEO; Part Description: CAP X7R 100nF +/-10% 10V CH0402 H0.55mm RO; Part Number: QT0012000328; Rev.Date: 2022-08-17
C0353 C0355 C0360 C0361 C0362 = C: Application_Level: Common(通用); DataRecord: 2017-08-09; Geometry Height: 0.5mm; Lib_Name: 电容; MPN: CC0402KRX7R7BB104; Manufacturer: YAGEO; Part Description: CAP X7R 100nF +/-10% 16V CH0402 H0.55mm RO; Part Number: QT0012100748; Rev.Date: 2022-08-17
D0301 D0359 = ESD5304D-10_TR: Application_Level: Common(通用); DataRecord: 2017-08-09; Geometry Height: 0.65mm; Lib_Name: ESD&EMI&TVS; Manufacturer: WILL; Part Description: TVS ARRAY Vrwm=5V 0.4pF DFN2510-10L; Part Number: QT0013501015; Rev.Date: 2022-09-13
D0302 D0303 D0353 = ESDU5V0F1: DataRecord: 2017-08-09; Geometry Height: 0.5mm; Lib_Name: ESD&EMI&TVS; Manufacturer: JCET; Part Description: TVS Si Vrwm=5V 0.5pF 1.0x0.6mm H0.5mm RO; Part Number: QT0013500188; Rev.Date: 2023-02-08
D0354 D0355 D0358 = PTVSHC2EN7VU: Application_Level: Common(通用); DataRecord: 2019-12-26; Geometry Height: 0.6mm; Lib_Name: ESD&EMI&TVS; Manufacturer: PRISEMI; Part Description: TVS Si Vrwm=7V 550pF 1.6x1.0mm H0.6mm RO; Part Number: QT0013501071; Rev.Date: 2022-09-20
D0356 D0357 = ESDU5V0F1: Application_Level: Common(通用); DataRecord: 2017-08-09; Geometry Height: 0.5mm; Lib_Name: ESD&EMI&TVS; Manufacturer: JCET; Part Description: TVS Si Vrwm=5V 0.5pF 1.0x0.6mm H0.5mm RO; Part Number: QT0013500188; Rev.Date: 2023-02-08
J0301 = W-N3-SC90-012: Application_Level: Limited(限制); BOMRemark: NSMT; DataRecord: 2022-06-30; Geometry Height: 15.87mm; Lib_Name: 结构连接器; Manufacturer: JCTC; Part Description: CON USB3.0 FEMALE 18PIN  17.5x14.5mm H15.87mm RO; Part Number: QT0016201747; Rev.Date: 2022-09-16
J0302 = WX4558105890: Application_Level: 限制（Others）; DataRecord: 2017-08-09; Geometry Height: 3.0mm; Lib_Name: 结构连接器; Manufacturer: WANGXING; Part Description: CON USBC MICRO FEMALE 5Pin 0.65pitch 8.0x5.6mm H3.0mm RO; Part Number: QT0016801005; Rev.Date: 2022-08-17
R0302 = R: DataRecord: 2017-08-09; Geometry Height: 0.4MM; Lib_Name: LIBRARY; MPN: RC0402JR-0710KL; Manufacturer: YAGEO; Part Description: RES MF 10K +/-5% 1/16W CH0402 H0.4mm RO; Part Number: QT0011000453; Rev.Date: 2022-08-17
R0305 = R-0402: Application_Level: Common(通用); BOMRemark: NM; DataRecord: 2017-08-09; Geometry Height: 0.4MM; Lib_Name: 电阻; MPN: RC0402FR-0747KL; Manufacturer: YAGEO; Part Description: RES MF 47K +/-5% 1/16W CH0402 H0.4mm RO; Part Number: QT0011000476; Rev.Date: 2021-12-15
R0308 = R-0402: Application_Level: Common(通用); DataRecord: 2017-08-09; Geometry Height: 0.4MM; Lib_Name: 电阻; MPN: RC0402JR-0747KL; Manufacturer: YAGEO; Part Description: RES MF 47K +/-5% 1/16W CH0402 H0.4mm RO; Part Number: QT0011000476; Rev.Date: 2022-08-17
R0309 = R-0402_0R: BOMRemark: NM; Part Description: RES MF 47K +/-5% 1/16W CH0402 H0.4mm RO; Part Number: QT0011000476
R0312 = R: DataRecord: 2017-08-09; Geometry Height: 0.4MM; Lib_Name: LIBRARY; MPN: RC0402JR-0715KL; Manufacturer: YAGEO; Part Description: RES MF 15K +/-5% 1/16W CH0402 H0.4mm RO; Part Number: QT0011000042; Rev.Date: 2022-08-17
R0313 = R-0402: Application_Level: Common(通用); BOMRemark: NM; DataRecord: 2017-08-09; Geometry Height: 0.4MM; Lib_Name: 电阻; MPN: RC0402JR-074K7L; Manufacturer: YAGEO; Part Description: RES MF 4.7K +/-5% 1/16W CH0402 H0.4mm RO; Part Number: QT0011000456; Rev.Date: 2021-12-15
R0325 = R-0402: Application_Level: 通用; DataRecord: 2017-08-09; Geometry Height: 0.4mm; Lib_Name: 电阻; MPN: RC0402JR-07100RL; Manufacturer: YAGEO; Part Description: RES MF 100R +/-5% 1/16W CH0402 H0.4mm RO; Part Number: QT0011000458; Rev.Date: 2022-08-17
R0366 = R-0603: Application_Level: 通用; BOMRemark: NM; DataRecord: 2017-08-09; Geometry Height: 0.55MM; Lib_Name: 电阻; MPN: RC0603JR-070RL; Manufacturer: YAGEO; Part Description: RES MF 0R +/-5% 1/10W CH0603 H0.55mm RO; Part Number: QT0011000610; Rev.Date: 2022-08-17
S0301 = SSAJ120100: Application_Level: Limited(限制); DataRecord: 2020-06-22; Geometry Height: 0.7mm; Lib_Name: 机械开关和按键; Manufacturer: ALPS; Part Description: SWITCH SLIDE 6.5x3.8mm H0.7mm RO; Part Number: QT0016401035; Rev.Date: 2021-12-15
U0304 = WS4612EDA-5_TR: Application_Level: Common(通用); DataRecord: 2022-03-17; Geometry Height: 1.25mm; Lib_Name: 电源管理芯片; MPN: WS4612EDA-5/TR; Manufacturer: WILL; Part Description: PMIC OCP 2.5-5.5V 2.4A 26uA SOT-23-5L H1.25mm RO; Part Number: QT0013101621; Rev.Date: 2023-03-20

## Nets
DVDD0_1V1: B0202.2 C0201.1 C0210.1 J0201.1
DVDD1_1V1: B0203.2 C0202.1 C0214.1 J0202.1
GND: C0102.1 C0103.1 C0104.1 C0105.1 C0106.1 C0107.1 C0108.1 C0109.1 C0110.1 C0112.1 C0115.1 C0116.1 C0118.1 C0119.1 C0121.1 C0122.1 C0123.1 C0124.1 C0126.1 C0127.1 C0128.1 C0201.2 C0202.2 C0203.2 C0204.1 C0205.1 C0206.2 C0207.1 C0208.1 C0209.1 C0210.2 C0212.1 C0213.1 C0214.2 C0215.1 C0216.1 C0217.1 C0301.1 C0303.1 C0319.1 C0352.2 C0353.2 C0354.2 C0355.2 C0362.1 C0363.1 D0101.2 D0102.1 D0301.3(GND1) D0301.8(GND2) D0302.2 D0303.2 D0353.2 D0354.2 D0355.2 D0356.2 D0357.2 D0358.2 D0359.3(GND1) D0359.8(GND2) J0101.2 J0101.3 J0101.4 J0101.5 J0201.4 J0201.8 J0201.11 J0201.15 J0201.18 J0201.23 J0201.26 J0201.27 J0202.4 J0202.8 J0202.11 J0202.15 J0202.18 J0202.23 J0202.26 J0202.27 J0301.4(GND1) J0301.7(GND-DRAIN1) J0301.13(GND2) J0301.16(GND-DRAIN2) J0301.19 J0301.20 J0301.21 J0301.22 J0302.5(GND1) J0302.6(GND2) J0302.7(GND3) J0302.8(GND4) J0302.9(GND5) J0302.10(GND6) J0302.11(GND7) R0101.2 R0103.1 R0108.1 R0110.1 R0112.2 R0114.2 R0203.1 R0204.1 R0219.1 R0223.1 R0224.1 R0227.2 R0228.2 R0309.1 R0312.1 R0313.1 S0301.3(2) S0301.4 S0301.5 TP0104.1 U0101.3(GND) U0103.3(GND) U0104.3(GND) U0201.5(GND1) U0201.6(GND2) U0202.2(GND) U0203.2(GND) U0204.2(GND) U0205.2(GND) U0206.5(GND1) U0206.6(GND2) U0207.5(GND1) U0207.6(GND2) U0208.5(GND1) U0208.6(GND2) U0209.5(GND1) U0209.6(GND2) U0210.5(GND1) U0210.6(GND2) U0304.2(GND) ; also on sheet 4 5 6 7 8 9 10 11 12 13 14
VBATT: C0107.2 C0119.2 C0123.2 C0204.2 C0205.2 C0213.2 C0215.2 J0102.1 L0103.2 R0115.1 R0120.2 U0202.1(IN) U0203.1(IN) U0204.3(IN) U0205.1(IN) ; also on sheet 5 11
VBATT_M: J0102.2 R0120.1 ; also on sheet 12 13
VBUS_USB_HOST1: C0362.2 C0363.2 D0358.1 J0301.10(VBUS2) ; also on sheet 6
VCC5V0_SYS: B0101.2 ; also on sheet 12
VCC5V0_USB: C0319.2 R0305.1 R0308.1 R0366.1 U0304.5(IN) ; also on sheet 6
VDD_AF0_2V8: C0203.1 J0201.3 R0229.2
VDD_AF1_2V8: C0206.1 J0202.3 R0209.2
90OHM_USB3_HOST1_DM_A: D0357.1 J0301.11(D2-) ; also on sheet 6
90OHM_USB3_HOST1_DP_A: D0356.1 J0301.12(D2+) ; also on sheet 6
90OHM_USB3_HOST1_SSRXN: R0341.2 ; also on sheet 12
90OHM_USB3_HOST1_SSRXN_A1: D0359.1(I/O1) D0359.10(NC4) J0301.14(StdA-SSR2-) R0341.1
90OHM_USB3_HOST1_SSRXP: R0340.2 ; also on sheet 12
90OHM_USB3_HOST1_SSRXP_A1: D0359.2(I/O2) D0359.9(NC3) J0301.15(StdA-SSR2+) R0340.1
90OHM_USB3_HOST1_SSTXN: C0361.2 ; also on sheet 12
90OHM_USB3_HOST1_SSTXN_A1: C0361.1 D0359.4(I/O3) D0359.7(NC2) J0301.17(StdA-SST2-)
90OHM_USB3_HOST1_SSTXP: C0360.2 ; also on sheet 12
90OHM_USB3_HOST1_SSTXP_A1: C0360.1 D0359.5(I/O4) D0359.6(NC1) J0301.18(StdA-SST2+)
90OHM_USB3_OTG0_DM: D0302.1 J0302.2(USB_DM) TP0301.1 ; also on sheet 12
90OHM_USB3_OTG0_DP: D0303.1 J0302.3(USB_DP) TP0302.1 ; also on sheet 12
90OHM_USB3_OTG0_SSRX_N: D0301.5(I/O4) D0301.6(NC1) J0301.5(StdA-SSR1-) R0322.1
90OHM_USB3_OTG0_SSRX_P: D0301.4(I/O3) D0301.7(NC2) J0301.6(StdA-SSR1+) R0323.1
90OHM_USB3_OTG0_SSRXN: R0322.2 ; also on sheet 12
90OHM_USB3_OTG0_SSRXP: R0323.2 ; also on sheet 12
90OHM_USB3_OTG0_SSTX_N: C0307.1 D0301.2(I/O2) D0301.9(NC3) J0301.8(StdA-SST1-)
90OHM_USB3_OTG0_SSTX_P: C0309.1 D0301.1(I/O1) D0301.10(NC4) J0301.9(StdA-SST1+)
90OHM_USB3_OTG0_SSTXN: C0307.2 ; also on sheet 12
90OHM_USB3_OTG0_SSTXP: C0309.2 ; also on sheet 12
100OHM_MIPI_CSI_RX_CLK0N: R0258.1 U0207.1 ; also on sheet 13
100OHM_MIPI_CSI_RX_CLK0N1: J0201.20 R0258.2 U0207.3
100OHM_MIPI_CSI_RX_CLK0P: R0257.1 U0207.2 ; also on sheet 13
100OHM_MIPI_CSI_RX_CLK0P1: J0201.19 R0257.2 U0207.4
100OHM_MIPI_CSI_RX_CLK1N: R0264.1 U0208.2 ; also on sheet 13
100OHM_MIPI_CSI_RX_CLK1N1: J0202.20 R0264.2 U0208.4
100OHM_MIPI_CSI_RX_CLK1P: R0263.1 U0208.1 ; also on sheet 13
100OHM_MIPI_CSI_RX_CLK1P1: J0202.19 R0263.2 U0208.3
100OHM_MIPI_CSI_RX_D0N: R0260.1 U0209.1 ; also on sheet 13
100OHM_MIPI_CSI_RX_D0N1: J0201.22 R0260.2 U0209.3
100OHM_MIPI_CSI_RX_D0P: R0259.1 U0209.2 ; also on sheet 13
100OHM_MIPI_CSI_RX_D0P1: J0201.21 R0259.2 U0209.4
100OHM_MIPI_CSI_RX_D1N: R0256.1 U0206.1 ; also on sheet 13
100OHM_MIPI_CSI_RX_D1N1: J0201.10 R0256.2 U0206.3
100OHM_MIPI_CSI_RX_D1P: R0255.1 U0206.2 ; also on sheet 13
100OHM_MIPI_CSI_RX_D1P1: J0201.9 R0255.2 U0206.4
100OHM_MIPI_CSI_RX_D2N: R0266.1 U0201.2 ; also on sheet 13
100OHM_MIPI_CSI_RX_D2N1: J0202.22 R0266.2 U0201.4
100OHM_MIPI_CSI_RX_D2P: R0265.1 U0201.1 ; also on sheet 13
100OHM_MIPI_CSI_RX_D2P1: J0202.21 R0265.2 U0201.3
100OHM_MIPI_CSI_RX_D3N: R0262.1 U0210.1 ; also on sheet 13
100OHM_MIPI_CSI_RX_D3N1: J0202.10 R0262.2 U0210.3
100OHM_MIPI_CSI_RX_D3P: R0261.1 U0210.2 ; also on sheet 13
100OHM_MIPI_CSI_RX_D3P1: J0202.9 R0261.2 U0210.4
CAM0_AVDD: B0201.2 J0201.16
CAM0_DOVDD_1V8: B0205.2 J0201.17
CAM0_PDN_L_GPIO3_D5: J0201.24 ; also on sheet 12
CAM0_RST_L_GPIO3_D4: J0201.14 ; also on sheet 12
CAM1_AVDD: B0204.2 J0202.16
CAM1_DOVDD_1V8: B0206.2 J0202.17
CAM1_MCLK: R0226.1 ; also on sheet 12
CAM1_PDN_L_GPIO3_D3: J0202.24 ; also on sheet 12
CAM1_RST_L_GPIO3_D2: J0202.14 ; also on sheet 12
CAM_DOVDD_1V8: B0205.1 B0206.1 C0209.2 C0299.1 R0207.2 R0208.2 R0212.2 R0221.2 R0222.2 U0205.5(OUT)
CMA0_MCLK: J0201.25 ; also on sheet 12
DC12V: C0102.2 C0103.2 C0108.2 C0110.2 C0112.2 C0115.2 C0116.2 C0118.2 C0121.2 C0122.2 C0127.2 C0128.2 D0101.1 F0101.2 R0104.2 R0106.2 R0113.2 R0116.1 R0117.2 TP0102.1 U0101.1(IN) U0103.1(IN) U0104.1(IN) ; also on sheet 5 6 9 14
EXT_EN: R0166.2 ; also on sheet 5 6 13
I2C2_SCL_M1: J0201.13 R0207.1 ; also on sheet 12
I2C2_SDA_M1: J0201.12 R0221.1 ; also on sheet 12
I2C3_SCL_M0: J0202.13 R0208.1 ; also on sheet 11 12
I2C3_SDA_M0: J0202.12 R0222.1 ; also on sheet 11 12
LCDC_D0: R0203.2 U0202.3(EN) ; also on sheet 12
LCDC_D9: R0204.2 U0204.5(EN) ; also on sheet 12
LCDC_D10: R0223.2 U0203.3(EN) ; also on sheet 12
LCDC_D12: R0228.1 U0205.3(EN) ; also on sheet 12
LCDC_HSYNC: R0319.1 ; also on sheet 12
USB3_OTG0_ID: R0325.2 S0301.2(C) ; also on sheet 12
USB3_OTG0_VBUSDET: R0302.2 R0312.2 ; also on sheet 12
USB_VBUS: C0301.2 C0303.2 C0352.1 C0353.1 C0354.1 C0355.1 D0354.1 D0355.1 J0301.1(VBUS1) J0302.1(VBUS) R0302.1 R0366.2 TP0303.1 U0304.1(OUT)
VDC_3V3: C0109.2 C0124.2 C0126.2 L0101.2 R0105.1 TP0103.1 ; also on sheet 4 5 8 10 11
VDC_5V: B0101.1 C0104.2 C0105.2 C0106.2 L0102.2 R0102.1 TP0101.1 ; also on sheet 4
N16762456: R0305.2 R0309.2 R0319.2 U0304.4(EN/~{EN})
N16762522: R0308.2 R0313.2 U0304.3(~{FLG})
N16831384: B0202.1 B0203.1 C0208.2 C0211.2 L0201.2 R0214.1 U0204.6(OUT)
N16831443: B0201.1 B0204.1 C0212.2 U0203.5(OUT)
N16831459: C0216.2 U0203.4(BP/FB)
N16831535: C0217.2 R0209.1 R0229.1 U0202.5(OUT)
N16831549: C0207.2 U0202.4(BP/FB)
N16832505: C0299.2 R0212.1 R0219.2 U0205.4(BP/FB)
N16833633: F0101.1 J0101.1 R0106.1
N17169242: J0202.25 R0226.2 R0227.1
N17310824: D0102.2 R0116.2
N17312479: R0101.1 R0104.1 U0101.5(EN)
N17312557: C0111.2 U0101.4(BST)
N17312561: C0111.1 L0103.1 U0101.2(SW)
N17312853: R0108.2 R0115.2 U0101.6(FB)
N17316601: R0103.2 R0113.1 R0166.1 U0103.5(EN)
N17316611: C0113.2 U0103.4(BST)
N17316621: C0113.1 L0101.1 U0103.2(SW)
N17316661: R0105.2 R0114.1 U0103.6(FB)
N17321443: R0110.2 R0117.1 U0104.5(EN)
N17321453: C0114.2 U0104.4(BST)
N17321455: C0114.1 L0102.1 U0104.2(SW)
N17321503: R0102.2 R0112.1 U0104.6(FB)
N18670938: L0201.1 U0204.4(SW)
N18671521: C0211.1 R0214.2 R0224.2 U0204.1(FB)
N19139644: D0353.1 J0302.4(USB_ID) R0325.1

Not connected (* = marked no-connect by the designer): J0201 2* 5* 6* 7*; J0202 2* 5* 6* 7*; J0301 2(D1-)* 3(D1+)*; S0301 1*

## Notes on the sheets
sheet 1
- DCDC VBAT 3.39V
- POWER_ON
- DC 12V
- 功耗测试点
- 4.5A
- Vout=0.805(1+R0115/R0108)=3.39V
- 4A
- POWER_ON LED
- SYSTEM 5V
- SYSTEM 3V3
- Vout=0.805(1+R0102/R0112)=5.007V
- 1.5A
- Vout=0.805(1+R0105/R0114)=3.327V
- 4A
- 4A
sheet 2
- CAMERA 0
- CAMERA 1
- CSI POWER
- Vout = 0.8(R0212+R0219)/R0219 = 1.854V
- 200mA
- 200mA
- 200mA
- 200mA
- Vout = 0.6(R0214+R0224)/R0224 = 1.15V
- 300mA
- 500mA
- 300mA
- 500mA
sheet 3
- TYPE-A  USB 3.0/2.0CONNECTER
- ESD
- MICRO CONNECTER
- 1.5A
- USB ID控制
